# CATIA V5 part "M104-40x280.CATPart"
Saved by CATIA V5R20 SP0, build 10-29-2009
Part number: M104-40x280
Source: Unknown
Bounding box of the stored display mesh (mm): x -19.994 to 19.994, y -19.994 to 19.994, z 0 to 280
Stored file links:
  C:\Users\Utente\Desktop\IO LAVORO\3D X SITO CF\X SITO\M104\M104-40x280.CATPart

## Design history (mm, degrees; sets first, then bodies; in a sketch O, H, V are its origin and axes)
Body1 (main body)
  Solid1 "PartBody": solid without history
